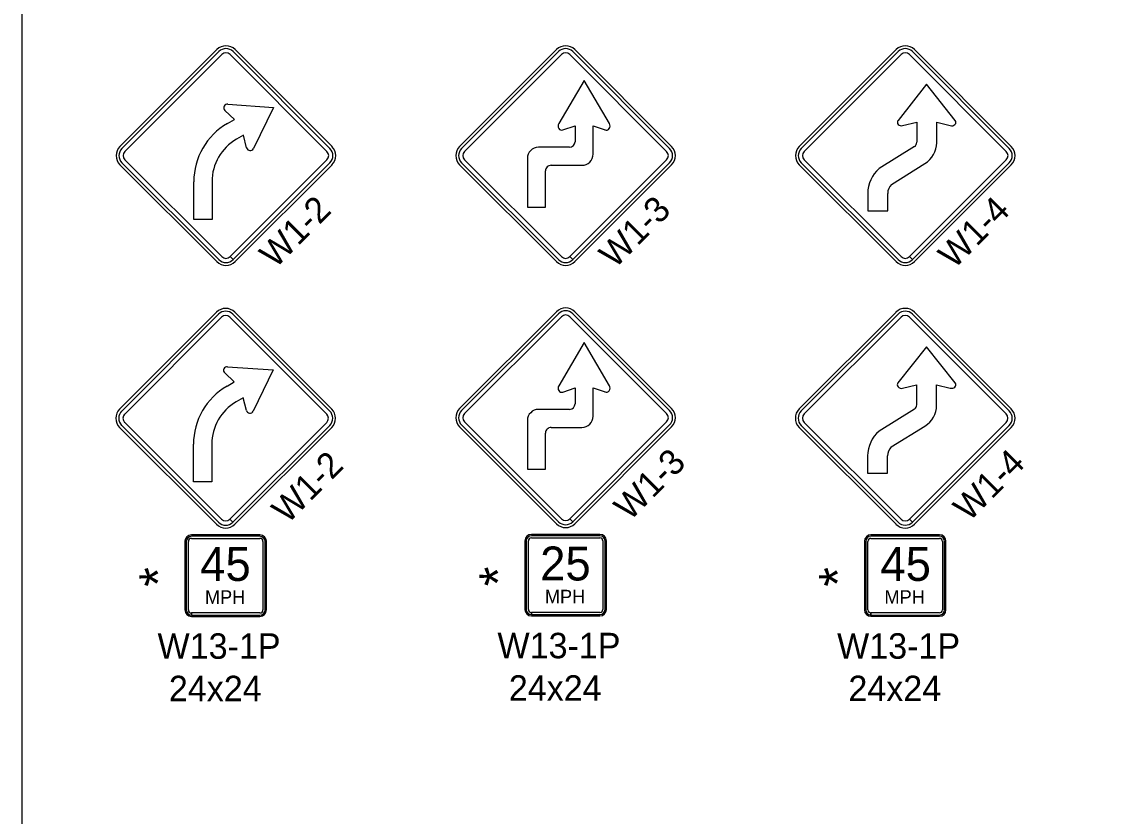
# Model space of a CAD drawing. Extents: x 1458 to 4498, y 17709 to 24109.
# Drawn here: x 1458 to 2100, y 23174 to 23641 of the extents above; entities that cross this region are included whole.
import ezdxf

# ---------------------------------------------------------------- set-up
doc = ezdxf.new("R2010")
doc.units = 0
doc.layers.add('P_TRAF_TCP_General', color=7, linetype='Continuous')

msp = doc.modelspace()

# ---------------------------------------------------------------- linework, layer by layer
at = {"layer": 'P_TRAF_TCP_General'}
for p, q in [((1573.24, 23624.96), (1516.24, 23567.95)), ((1574.43, 23623.78), (1517.42, 23566.77)), ((1574.43, 23623.78), (1517.42, 23566.77)), ((1519.19, 23565), (1576.19, 23622.01)), ((1519.19, 23565), (1576.19, 23622.01)), ((1581.14, 23622.01), (1638.15, 23565)), ((1581.14, 23622.01), (1638.15, 23565)), ((1639.91, 23566.77), (1582.91, 23623.78)), ((1639.91, 23566.77), (1582.91, 23623.78)), ((1641.1, 23567.95), (1584.09, 23624.96)), ((1773.24, 23624.96), (1716.24, 23567.95)), ((1774.43, 23623.78), (1717.42, 23566.77)), ((1774.43, 23623.78), (1717.42, 23566.77)), ((1719.19, 23565), (1776.19, 23622.01)), ((1719.19, 23565), (1776.19, 23622.01)), ((1781.14, 23622.01), (1838.15, 23565)), ((1781.14, 23622.01), (1838.15, 23565)), ((1839.91, 23566.77), (1782.91, 23623.78)), ((1839.91, 23566.77), (1782.91, 23623.78)), ((1841.1, 23567.95), (1784.09, 23624.96)), ((1973.24, 23624.96), (1916.24, 23567.95)), ((1974.43, 23623.78), (1917.42, 23566.77)), ((1974.43, 23623.78), (1917.42, 23566.77)), ((1919.19, 23565), (1976.19, 23622.01)), ((1919.19, 23565), (1976.19, 23622.01)), ((1981.14, 23622.01), (2038.15, 23565)), ((1981.14, 23622.01), (2038.15, 23565)), ((2039.91, 23566.77), (1982.91, 23623.78)), ((2039.91, 23566.77), (1982.91, 23623.78)), ((2041.1, 23567.95), (1984.09, 23624.96)), ((1789.54, 23606.84), (1774.59, 23581.37)), ((1804.49, 23581.38), (1789.54, 23606.84)), ((1991.25, 23604.63), (1974.4, 23583.31)), ((2008.09, 23583.31), (1991.25, 23604.63)), ((1583.63, 23583.87), (1578.09, 23589.18)), ((1579.79, 23592.89), (1606.65, 23590.96)), ((1606.65, 23590.96), (1594.88, 23566.69)), ((1579.5, 23581.49), (1583.63, 23583.87)), ((1977.06, 23580.18), (1985.41, 23582.26)), ((1985.41, 23582.26), (1985.41, 23570.43)), ((1997.18, 23582.23), (2005.12, 23580.28)), ((1997.18, 23570.14), (1997.18, 23582.23)), ((1589, 23574.56), (1584.85, 23572.16)), ((1590.83, 23567.11), (1589, 23574.56)), ((1776.97, 23577.64), (1784.23, 23580.07)), ((1784.23, 23580.07), (1784.23, 23570.73)), ((1794.85, 23563.42), (1794.85, 23580.07)), ((1794.85, 23580.07), (1801.85, 23577.75)), ((1780.95, 23567.45), (1762.71, 23567.45)), ((1984.04, 23567.93), (1963.23, 23554.92)), ((1516.24, 23557.11), (1573.24, 23500.1)), ((1517.42, 23558.29), (1574.43, 23501.28)), ((1517.42, 23558.29), (1574.43, 23501.28)), ((1576.19, 23503.05), (1519.19, 23560.06)), ((1638.15, 23560.06), (1581.16, 23503.07)), ((1638.15, 23560.06), (1581.16, 23503.07)), ((1582.93, 23501.3), (1639.91, 23558.29)), ((1582.93, 23501.3), (1639.91, 23558.29)), ((1584.09, 23500.1), (1641.1, 23557.11)), ((1716.24, 23557.11), (1773.24, 23500.1)), ((1717.42, 23558.29), (1774.43, 23501.28)), ((1717.42, 23558.29), (1774.43, 23501.28)), ((1776.19, 23503.05), (1719.19, 23560.06)), ((1756.18, 23560.88), (1756.18, 23532.15)), ((1770.13, 23556.82), (1788.29, 23556.82)), ((1838.15, 23560.06), (1781.16, 23503.07)), ((1838.15, 23560.06), (1781.16, 23503.07)), ((1782.93, 23501.3), (1839.91, 23558.29)), ((1782.93, 23501.3), (1839.91, 23558.29)), ((1784.09, 23500.1), (1841.1, 23557.11)), ((1916.24, 23557.11), (1973.24, 23500.1)), ((1917.42, 23558.29), (1974.43, 23501.28)), ((1976.19, 23503.05), (1919.19, 23560.06)), ((1970.48, 23545.57), (1990.19, 23557.89)), ((2038.15, 23560.06), (1981.16, 23503.07)), ((2038.15, 23560.06), (1981.16, 23503.07)), ((1982.93, 23501.3), (2039.91, 23558.29)), ((1982.93, 23501.3), (2039.91, 23558.29)), ((1984.09, 23500.1), (2041.1, 23557.11)), ((1766.81, 23532.17), (1766.81, 23553.54)), ((1559.7, 23525), (1559.7, 23547.19)), ((1570.45, 23547.22), (1570.45, 23525)), ((1956.53, 23540.32), (1956.55, 23530.1)), ((1968.31, 23530.12), (1968.3, 23540.32)), ((1756.18, 23532.15), (1766.81, 23532.17)), ((1956.55, 23530.1), (1968.31, 23530.12)), ((1570.45, 23525), (1559.7, 23525)), ((1582.91, 23501.28), (1581.14, 23503.05)), ((1582.91, 23501.28), (1581.14, 23503.05)), ((1581.16, 23503.07), (1582.93, 23501.3)), ((1581.16, 23503.07), (1582.93, 23501.3)), ((1782.91, 23501.28), (1781.14, 23503.05)), ((1782.91, 23501.28), (1781.14, 23503.05)), ((1781.16, 23503.07), (1782.93, 23501.3)), ((1781.16, 23503.07), (1782.93, 23501.3)), ((1982.91, 23501.28), (1981.14, 23503.05)), ((1982.91, 23501.28), (1981.14, 23503.05)), ((1981.16, 23503.07), (1982.93, 23501.3)), ((1981.16, 23503.07), (1982.93, 23501.3)), ((1573.07, 23470.33), (1516.07, 23413.33)), ((1574.26, 23469.15), (1517.25, 23412.14)), ((1519.02, 23410.37), (1576.02, 23467.38)), ((1580.97, 23467.38), (1637.98, 23410.37)), ((1639.74, 23412.14), (1582.74, 23469.15)), ((1640.93, 23413.33), (1583.92, 23470.33)), ((1773.24, 23470.61), (1716.24, 23413.61)), ((1774.43, 23469.43), (1717.42, 23412.42)), ((1774.43, 23469.43), (1717.42, 23412.42)), ((1719.19, 23410.66), (1776.19, 23467.66)), ((1781.14, 23467.66), (1838.15, 23410.66)), ((1839.91, 23412.42), (1782.91, 23469.43)), ((1839.91, 23412.42), (1782.91, 23469.43)), ((1841.1, 23413.61), (1784.09, 23470.61)), ((1973.2, 23470.36), (1916.19, 23413.36)), ((1974.38, 23469.18), (1917.38, 23412.17)), ((1919.14, 23410.41), (1976.15, 23467.41)), ((1981.1, 23467.41), (2038.1, 23410.41)), ((2039.87, 23412.17), (1982.86, 23469.18)), ((2039.87, 23412.17), (1982.86, 23469.18)), ((2041.05, 23413.36), (1984.05, 23470.36)), ((1789.54, 23452.5), (1774.59, 23427.03)), ((1804.49, 23427.03), (1789.54, 23452.5)), ((1991.2, 23450.03), (1974.36, 23428.72)), ((2008.05, 23428.72), (1991.2, 23450.03)), ((1583.46, 23429.24), (1577.92, 23434.55)), ((1579.62, 23438.26), (1606.48, 23436.33)), ((1606.48, 23436.33), (1594.7, 23412.06)), ((1579.32, 23426.86), (1583.46, 23429.24)), ((1977.02, 23425.58), (1985.36, 23427.66)), ((1985.36, 23427.66), (1985.36, 23415.84)), ((1997.13, 23427.64), (2005.07, 23425.68)), ((1997.13, 23415.54), (1997.13, 23427.64)), ((1776.97, 23423.3), (1784.23, 23425.72)), ((1784.23, 23425.72), (1784.23, 23416.38)), ((1794.85, 23409.07), (1794.85, 23425.72)), ((1794.85, 23425.72), (1801.85, 23423.41)), ((1588.83, 23419.93), (1584.68, 23417.53)), ((1590.66, 23412.48), (1588.83, 23419.93)), ((1780.95, 23413.1), (1762.71, 23413.1)), ((1984, 23413.33), (1963.19, 23400.32)), ((1516.07, 23402.48), (1573.07, 23345.47)), ((1517.25, 23403.66), (1574.26, 23346.65)), ((1576.02, 23348.42), (1519.02, 23405.43)), ((1637.98, 23405.43), (1580.99, 23348.44)), ((1582.76, 23346.67), (1639.74, 23403.66)), ((1583.92, 23345.47), (1640.93, 23402.48)), ((1716.24, 23402.76), (1773.24, 23345.75)), ((1717.42, 23403.94), (1774.43, 23346.94)), ((1776.19, 23348.7), (1719.19, 23405.71)), ((1756.18, 23406.54), (1756.18, 23377.81)), ((1770.13, 23402.48), (1788.29, 23402.48)), ((1838.15, 23405.71), (1781.16, 23348.72)), ((1782.93, 23346.95), (1839.91, 23403.94)), ((1784.09, 23345.75), (1841.1, 23402.76)), ((1916.19, 23402.51), (1973.2, 23345.5)), ((1917.38, 23403.69), (1974.38, 23346.69)), ((1976.15, 23348.45), (1919.14, 23405.46)), ((1970.43, 23390.97), (1990.15, 23403.3)), ((2038.1, 23405.46), (1981.11, 23348.47)), ((1982.88, 23346.7), (2039.87, 23403.69)), ((1984.05, 23345.5), (2041.05, 23402.51)), ((1766.81, 23377.82), (1766.81, 23399.2)), ((1559.52, 23370.37), (1559.52, 23392.56)), ((1570.28, 23392.59), (1570.28, 23370.37)), ((1956.49, 23385.73), (1956.5, 23375.5)), ((1968.27, 23375.52), (1968.25, 23385.73)), ((1756.18, 23377.81), (1766.81, 23377.82)), ((1570.28, 23370.37), (1559.52, 23370.37)), ((1956.5, 23375.5), (1968.27, 23375.52)), ((1582.74, 23346.65), (1580.97, 23348.42)), ((1582.74, 23346.65), (1580.97, 23348.42)), ((1580.99, 23348.44), (1582.76, 23346.67)), ((1580.99, 23348.44), (1582.76, 23346.67)), ((1782.91, 23346.94), (1781.14, 23348.7)), ((1782.91, 23346.94), (1781.14, 23348.7)), ((1781.16, 23348.72), (1782.93, 23346.95)), ((1781.16, 23348.72), (1782.93, 23346.95)), ((1982.86, 23346.69), (1981.1, 23348.45)), ((1982.86, 23346.69), (1981.1, 23348.45)), ((1981.11, 23348.47), (1982.88, 23346.7)), ((1981.11, 23348.47), (1982.88, 23346.7)), ((1598.69, 23339.22), (1558.31, 23339.22)), ((1598.69, 23338.37), (1558.31, 23338.37)), ((1798.86, 23339.51), (1758.48, 23339.51)), ((1798.86, 23338.65), (1758.48, 23338.65)), ((1798.86, 23338.65), (1758.48, 23338.65)), ((1758.48, 23337.4), (1798.86, 23337.4)), ((1998.81, 23339.26), (1958.43, 23339.26)), ((1998.81, 23338.4), (1958.43, 23338.4)), ((1554.51, 23335.43), (1554.51, 23295.04)), ((1555.31, 23335.37), (1555.31, 23294.98)), ((1556.56, 23294.98), (1556.56, 23335.37)), ((1558.31, 23337.12), (1598.69, 23337.12)), ((1600.44, 23335.37), (1600.44, 23294.98)), ((1601.69, 23294.98), (1601.69, 23335.37)), ((1602.49, 23295.04), (1602.49, 23335.43)), ((1754.68, 23335.71), (1754.68, 23295.33)), ((1755.48, 23335.65), (1755.48, 23295.27)), ((1755.48, 23335.65), (1755.48, 23295.27)), ((1756.73, 23295.27), (1756.73, 23335.65)), ((1800.61, 23335.65), (1800.61, 23295.27)), ((1801.86, 23295.27), (1801.86, 23335.65)), ((1801.86, 23295.27), (1801.86, 23335.65)), ((1802.66, 23295.33), (1802.66, 23335.71)), ((1954.63, 23335.46), (1954.63, 23295.07)), ((1955.43, 23335.4), (1955.43, 23295.02)), ((1956.68, 23295.02), (1956.68, 23335.4)), ((1958.43, 23337.15), (1998.81, 23337.15)), ((2000.56, 23335.4), (2000.56, 23295.02)), ((2001.81, 23295.02), (2001.81, 23335.4)), ((2002.61, 23295.07), (2002.61, 23335.46)), ((1558.31, 23291.99), (1558.31, 23293.23)), ((1598.69, 23293.23), (1558.32, 23293.23)), ((1558.32, 23293.23), (1558.32, 23291.99)), ((1758.48, 23292.27), (1758.48, 23293.52)), ((1798.86, 23293.52), (1758.49, 23293.52)), ((1758.49, 23293.52), (1758.49, 23292.27)), ((1958.43, 23292.02), (1958.43, 23293.27)), ((1998.81, 23293.27), (1958.44, 23293.27)), ((1958.44, 23293.27), (1958.44, 23292.02)), ((1558.31, 23291.24), (1598.69, 23291.24)), ((1558.32, 23291.99), (1598.69, 23291.99)), ((1758.48, 23292.27), (1798.86, 23292.27)), ((1758.48, 23291.53), (1798.86, 23291.53)), ((1758.49, 23292.27), (1798.86, 23292.27)), ((1958.43, 23291.28), (1998.81, 23291.28)), ((1958.44, 23292.02), (1998.81, 23292.02))]:
    msp.add_line(p, q, dxfattribs=at)
msp.add_lwpolyline([(4498.44, 24109.14), (1458.44, 24109.14), (1458.44, 22109.14), (4498.44, 22109.14)], close=True, dxfattribs=at)
for centre, radius, start, end in [((1578.67, 23619.54), 7.67, 45, 135), ((1778.67, 23619.54), 7.67, 45, 135), ((1978.67, 23619.54), 7.67, 45, 135), ((1578.67, 23619.54), 6, 45, 135), ((1578.67, 23619.54), 6, 45, 135), ((1578.67, 23619.54), 3.5, 45, 135), ((1578.67, 23619.54), 3.5, 45, 135), ((1778.67, 23619.54), 6, 45, 135), ((1778.67, 23619.54), 6, 45, 135), ((1778.67, 23619.54), 3.5, 45, 135), ((1778.67, 23619.54), 3.5, 45, 135), ((1978.67, 23619.54), 6, 45, 135), ((1978.67, 23619.54), 6, 45, 135), ((1978.67, 23619.54), 3.5, 45, 135), ((1978.67, 23619.54), 3.5, 45, 135), ((1579.59, 23590.74), 2.16, 84.59635, 226.18136), ((1599.29, 23547.19), 39.6, 120.00009, 180), ((1599.25, 23547.22), 28.8, 120.00016, 179.99981), ((1780.94, 23570.73), 3.28, 270, 0), ((1982.61, 23570.33), 2.8, 300.7657, 2.07722), ((1982.61, 23570.33), 14.57, 301.35342, 359.25164), ((1521.66, 23562.53), 7.67, 135, 225), ((1521.66, 23562.53), 6, 135, 225), ((1521.66, 23562.53), 6, 135, 225), ((1521.66, 23562.53), 3.5, 135, 225), ((1521.66, 23562.53), 3.5, 135, 225), ((1592.93, 23567.63), 2.16, 193.8183, 334.11463), ((1635.67, 23562.53), 3.5, 315, 45), ((1635.67, 23562.53), 3.5, 315, 45), ((1635.67, 23562.53), 6, 315, 45), ((1635.67, 23562.53), 6, 315, 45), ((1635.67, 23562.53), 7.67, 315, 45), ((1721.66, 23562.53), 7.67, 135, 225), ((1721.66, 23562.53), 6, 135, 225), ((1721.66, 23562.53), 6, 135, 225), ((1721.66, 23562.53), 3.5, 135, 225), ((1721.66, 23562.53), 3.5, 135, 225), ((1762.75, 23560.88), 6.57, 90.37312, 180), ((1788.29, 23563.39), 6.57, 270, 0.25767), ((1835.67, 23562.53), 3.5, 315, 45), ((1835.67, 23562.53), 3.5, 315, 45), ((1835.67, 23562.53), 6, 315, 45), ((1835.67, 23562.53), 6, 315, 45), ((1835.67, 23562.53), 7.67, 315, 45), ((1921.66, 23562.53), 7.67, 135, 225), ((1921.66, 23562.53), 6, 135, 225), ((1921.66, 23562.53), 6, 135, 225), ((1921.66, 23562.53), 3.5, 135, 225), ((1921.66, 23562.53), 3.5, 135, 225), ((2035.67, 23562.53), 3.5, 315, 45), ((2035.67, 23562.53), 3.5, 315, 45), ((2035.67, 23562.53), 6, 315, 45), ((2035.67, 23562.53), 6, 315, 45), ((2035.67, 23562.53), 7.67, 315, 45), ((1770.09, 23553.54), 3.28, 89.32933, 180), ((1976.34, 23540.07), 19.8, 131.42399, 179.25716), ((1976.2, 23540.12), 7.91, 136.41117, 178.49859), ((1578.67, 23505.52), 7.67, 225, 315), ((1578.67, 23505.52), 6, 225, 315), ((1578.67, 23505.52), 6, 225, 315), ((1578.67, 23505.52), 3.5, 225, 315), ((1578.67, 23505.52), 3.5, 225, 315), ((1778.67, 23505.52), 7.67, 225, 315), ((1778.67, 23505.52), 6, 225, 315), ((1778.67, 23505.52), 6, 225, 315), ((1778.67, 23505.52), 3.5, 225, 315), ((1778.67, 23505.52), 3.5, 225, 315), ((1978.67, 23505.52), 7.67, 225, 315), ((1978.67, 23505.52), 6, 225, 315), ((1978.67, 23505.52), 6, 225, 315), ((1978.67, 23505.52), 3.5, 225, 315), ((1978.67, 23505.52), 3.5, 225, 315), ((1578.5, 23464.91), 7.67, 45, 135), ((1778.67, 23465.19), 7.67, 45, 135), ((1978.62, 23464.94), 7.67, 45, 135), ((1578.5, 23464.91), 6, 45, 135), ((1578.5, 23464.91), 3.5, 45, 135), ((1578.5, 23464.91), 3.5, 45, 135), ((1778.67, 23465.19), 6, 45, 135), ((1778.67, 23465.19), 3.5, 45, 135), ((1978.62, 23464.94), 6, 45, 135), ((1978.62, 23464.94), 3.5, 45, 135), ((1579.42, 23436.11), 2.16, 84.59635, 226.18136), ((1599.12, 23392.56), 39.6, 120.00009, 180), ((1599.08, 23392.59), 28.8, 120.00016, 179.99981), ((1780.95, 23416.39), 3.28, 270, 0), ((1982.57, 23415.74), 2.8, 300.7657, 2.07722), ((1982.57, 23415.74), 14.57, 301.35342, 359.25164), ((1521.49, 23407.9), 7.67, 135, 225), ((1521.49, 23407.9), 6, 135, 225), ((1521.49, 23407.9), 3.5, 135, 225), ((1521.49, 23407.9), 3.5, 135, 225), ((1592.76, 23413), 2.16, 193.8183, 334.11463), ((1635.5, 23407.9), 3.5, 315, 45), ((1635.5, 23407.9), 3.5, 315, 45), ((1635.5, 23407.9), 6, 315, 45), ((1635.5, 23407.9), 7.67, 315, 45), ((1721.66, 23408.18), 7.67, 135, 225), ((1721.66, 23408.18), 6, 135, 225), ((1721.66, 23408.18), 3.5, 135, 225), ((1762.75, 23406.54), 6.57, 90.37312, 180), ((1788.29, 23409.04), 6.57, 270, 0.25767), ((1835.67, 23408.18), 3.5, 315, 45), ((1835.67, 23408.18), 6, 315, 45), ((1835.67, 23408.18), 7.67, 315, 45), ((1921.62, 23407.93), 7.67, 135, 225), ((1921.62, 23407.93), 6, 135, 225), ((1921.62, 23407.93), 3.5, 135, 225), ((2035.63, 23407.93), 3.5, 315, 45), ((2035.63, 23407.93), 6, 315, 45), ((2035.63, 23407.93), 7.67, 315, 45), ((1770.09, 23399.2), 3.28, 89.32933, 180), ((1976.29, 23385.47), 19.8, 131.42399, 179.25716), ((1976.16, 23385.52), 7.91, 136.41117, 178.49859), ((1578.5, 23350.89), 7.67, 225, 315), ((1578.5, 23350.89), 6, 225, 315), ((1578.5, 23350.89), 3.5, 225, 315), ((1778.67, 23351.18), 7.67, 225, 315), ((1778.67, 23351.18), 6, 225, 315), ((1778.67, 23351.18), 6, 225, 315), ((1778.67, 23351.18), 3.5, 225, 315), ((1978.62, 23350.93), 7.67, 225, 315), ((1978.62, 23350.93), 6, 225, 315), ((1978.62, 23350.93), 6, 225, 315), ((1978.62, 23350.93), 3.5, 225, 315), ((1558.31, 23335.43), 3.8, 90, 180), ((1558.31, 23335.37), 3, 90, 180), ((1598.69, 23335.43), 3.8, 0, 90), ((1598.69, 23335.37), 3, 0, 90), ((1758.48, 23335.71), 3.8, 90, 180), ((1758.48, 23335.65), 3, 90, 180), ((1758.48, 23335.65), 3, 90, 180), ((1758.48, 23335.65), 1.75, 90, 180), ((1798.86, 23335.71), 3.8, 0, 90), ((1798.86, 23335.65), 3, 0, 90), ((1798.86, 23335.65), 3, 0, 90), ((1798.86, 23335.65), 1.75, 0, 90), ((1958.43, 23335.46), 3.8, 90, 180), ((1958.43, 23335.4), 3, 90, 180), ((1998.81, 23335.46), 3.8, 0, 90), ((1998.81, 23335.4), 3, 0, 90), ((1558.31, 23335.37), 1.75, 90, 180), ((1598.69, 23335.37), 1.75, 0, 90), ((1958.43, 23335.4), 1.75, 90, 180), ((1998.81, 23335.4), 1.75, 0, 90), ((1558.31, 23295.04), 3.8, 180, 270), ((1558.31, 23294.98), 3, 180, 270), ((1558.31, 23294.98), 1.75, 180, 270), ((1598.69, 23295.04), 3.8, 270, 0), ((1598.69, 23294.98), 3, 270, 0), ((1598.69, 23294.98), 1.75, 270, 0), ((1758.48, 23295.33), 3.8, 180, 270), ((1758.48, 23295.27), 3, 180, 270), ((1758.48, 23295.27), 3, 180, 270), ((1758.48, 23295.27), 1.75, 180, 270), ((1798.86, 23295.33), 3.8, 270, 0), ((1798.86, 23295.27), 3, 270, 0), ((1798.86, 23295.27), 3, 270, 0), ((1798.86, 23295.27), 1.75, 270, 0), ((1958.43, 23295.07), 3.8, 180, 270), ((1958.43, 23295.02), 3, 180, 270), ((1958.43, 23295.02), 1.75, 180, 270), ((1998.81, 23295.07), 3.8, 270, 0), ((1998.81, 23295.02), 3, 270, 0), ((1998.81, 23295.02), 1.75, 270, 0)]:
    msp.add_arc(centre, radius, start, end, dxfattribs=at)
for centre, major_axis, ratio, start_param, end_param in [((1776.36, 23580), (0, -2.46), 0.866667, 4.12007, 6.576152), ((1802.72, 23580), (0, 2.46), 0.866667, 2.720078, 5.307799), ((1976.39, 23582.16), (-2.4, 0), 0.857143, 5.687775, 8.136408), ((2006.1, 23582.16), (-2.4, 0), 0.857143, 1.149282, 3.737003), ((1776.36, 23425.65), (0, -2.46), 0.866667, 4.12007, 6.576152), ((1802.72, 23425.65), (0, 2.46), 0.866667, 2.720078, 5.307799), ((1976.35, 23427.56), (-2.4, 0), 0.857143, 5.687775, 8.136408), ((2006.05, 23427.56), (-2.4, 0), 0.857143, 1.149282, 3.737003)]:
    msp.add_ellipse(centre, major_axis=major_axis, ratio=ratio, start_param=start_param, end_param=end_param, dxfattribs=at)

# ---------------------------------------------------------------- texts
for s, height, rotation, p in [('W1-2', 14.994, 45, (1607.65, 23495.64)), ('W1-3', 14.994, 45, (1807.61, 23495.59)), ('W1-4', 14.994, 45, (2007.31, 23495.3)), ('W1-3', 14.994, 45, (1816.42, 23346.88)), ('W1-4', 14.994, 45, (2016.21, 23346.46)), ('W1-2', 14.994, 45, (1614.88, 23345.23)), ('*', 22.14, 90, (1549.74, 23308.67)), ('*', 22.14, 90, (1749.9, 23309)), ('*', 22.14, 90, (1949.92, 23308.7))]:
    msp.add_text(s, height=height, rotation=rotation, dxfattribs=at).set_placement(p)
for s, height, p in [('45', 19.992, (1563.51, 23312.08)), ('25', 19.992, (1763.68, 23312.36)), ('45', 19.992, (1964.02, 23312.11)), ('MPH', 7.997, (1566.27, 23298.59)), ('MPH', 7.997, (1766.45, 23298.87)), ('MPH', 7.997, (1966.4, 23298.62)), ('W13-1P', 14.994, (1538.38, 23266.25)), ('W13-1P', 14.994, (1738.55, 23266.54)), ('W13-1P', 14.994, (1938.51, 23266.29)), ('24x24', 14.994, (1545.05, 23241.26)), ('24x24', 14.994, (1745.22, 23241.55)), ('24x24', 14.994, (1945.18, 23241.3))]:
    msp.add_text(s, height=height, dxfattribs=at).set_placement(p)

doc.saveas('drawing.dxf')
